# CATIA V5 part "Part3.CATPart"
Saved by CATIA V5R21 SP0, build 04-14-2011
Part number: Part3
Bounding box of the stored display mesh (mm): x 0 to 0, y -40 to 40, z -40 to 40
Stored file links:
  D:\CATIA V5R21 E-RESOURCES\CATIA-V5R21\catia-v5r21-Prts\c16_catia_v5r21_prt\Slide Curve Joint-(Fig16-40)\Part3.CATPart
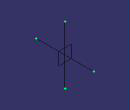
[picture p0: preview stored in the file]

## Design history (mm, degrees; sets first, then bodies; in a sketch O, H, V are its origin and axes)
Body1 (main body)
  Sketch1 on yz-plane, origin (0, 0, 0), H (0, 1, 0), V (0, 0, 1)
    line L1 (0, 40) -> (0, -40)
    point P1 (0, 40)
    point P2 (0, -40)
    line L2 (40, 0) -> (-40, 0)
    point P3 (40, 0)
    length L1 = 80
    length L2 = 80
    distance L1 P3 = 40
    distance P2 L2 = 40
    coincidence: P1 V, P3 H
    vertical: L1 V
    horizontal: L2 H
